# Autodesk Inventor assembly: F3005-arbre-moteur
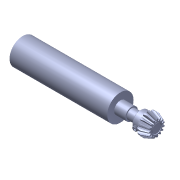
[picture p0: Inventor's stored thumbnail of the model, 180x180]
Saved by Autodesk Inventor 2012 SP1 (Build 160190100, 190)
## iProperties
Created: 2014-12
Part Number: F3005-arbre-moteur
Document SubType Name: Assembly
Designer: Bruno
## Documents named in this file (4)
- D:\Cours\Systèmes\secateur-hydrogene-Pragma\Documentation\Dossier technique Infaco F3005\Solidworks\Composants importés\F3005-arbre-moteur.iam
- D:\Cours\Systèmes\secateur-hydrogene-Pragma\Documentation\Dossier technique Infaco F3005\Solidworks\Composants importés\F3005\Pignon 15dts.ipt
- D:\Cours\Systèmes\secateur-hydrogene-Pragma\Documentation\Dossier technique Infaco F3005\Solidworks\Composants importés\F3005\Vis pignon 15dts.ipt
- D:\Cours\Systèmes\secateur-hydrogene-Pragma\Documentation\Dossier technique Infaco F3005\Solidworks\Composants importés\F3005\Bobine moteur.ipt
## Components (3 placed, 3 different names)
1. Pignon 15dts:1 — Placage:1, Affleurement:1, Affleurement:2
2. Vis pignon 15dts:1 — Placage:2
3. Bobine moteur:1 — Placage:1, Placage:2, Affleurement:1
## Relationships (4: Mate 2, Flush 2)
- Placage:1 [Mate]: Pignon 15dts:1 ↔ Bobine moteur:1
- Placage:2 [Mate]: Vis pignon 15dts:1 ↔ Bobine moteur:1
- Affleurement:1 [Flush]: Pignon 15dts:1 ↔ Bobine moteur:1
- Affleurement:2 [Flush]: Pignon 15dts:1
